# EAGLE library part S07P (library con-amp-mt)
AMP MT CONNECTOR
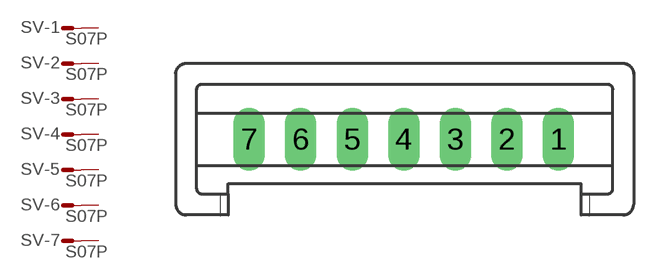
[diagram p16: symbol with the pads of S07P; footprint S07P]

Designator prefix SV; gates -1=M -2=M -3=M -4=M -5=M -6=M -7=M

## S07P (OC_FARNELL: unknown; OC_NEWARK: unknown)  [S07P]
1  -1:S  pas
2  -2:S  pas
3  -3:S  pas
4  -4:S  pas
5  -5:S  pas
6  -6:S  pas
7  -7:S  pas

## Footprint S07P (pad centres in mm)
AMP MT CONNECTOR
drill 1.016 long: 1 7.5,0; 2 5,0; 3 2.5,0; 4 0,0; 5 -2.5,0; 6 -5,0; 7 -7.5,0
